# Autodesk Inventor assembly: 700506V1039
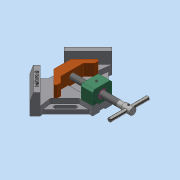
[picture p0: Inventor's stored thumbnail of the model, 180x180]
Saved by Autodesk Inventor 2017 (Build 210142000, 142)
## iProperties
Part Number: 700506V1039
Material: 일반
Document SubType Name: Assembly
Designer: 00-00
Author: 00-00
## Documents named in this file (11)
- C:\Users\00-00\Desktop\700506V1039\700506V1039.iam
- C:\Users\00-00\Desktop\700506V1039\베이스.ipt
- C:\Users\00-00\Desktop\700506V1039\리드스크류.ipt
- C:\Users\00-00\Desktop\700506V1039\멈춤나사 M4x5.ipt
- C:\Users\00-00\Desktop\700506V1039\멈춤나사 M4x10.ipt
- C:\Users\00-00\Desktop\700506V1039\볼트 M4x16.ipt
- C:\Users\00-00\Desktop\700506V1039\부시.ipt
- C:\Users\00-00\Desktop\700506V1039\서포트.ipt
- C:\Users\00-00\Desktop\700506V1039\조.ipt
- C:\Users\00-00\Desktop\700506V1039\평행 핀 2.5x24.ipt
- C:\Users\00-00\Desktop\700506V1039\핸들.ipt
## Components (1 placed, 1 different names)
1. 핸들:1
## Component patterns: 구성요소 패턴 1:2 (2 elements)
